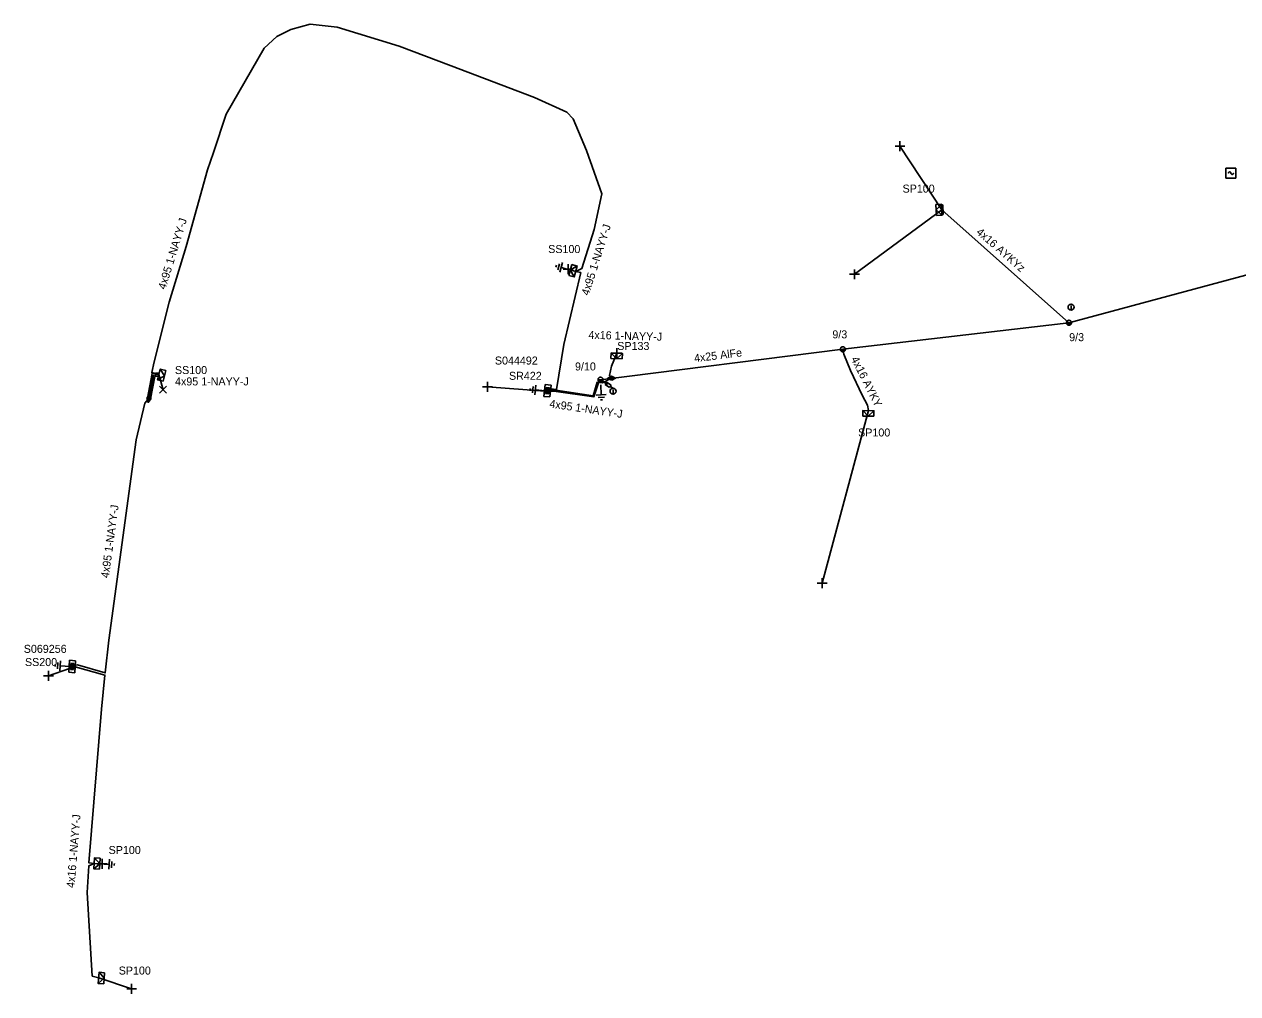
# Model space of a CAD drawing. Extents: x -717562 to -713845, y -1151196 to -1143903.
# Drawn here: x -717327.7 to -717176.1, y -1144131.3 to -1144010.2 of the extents above; entities that cross this region are included whole.
import ezdxf

# ---------------------------------------------------------------- set-up
doc = ezdxf.new("R2010")
doc.units = 0
for name, color, linetype in [('Vrstva 1', 7, 'Continuous'), ('Vrstva 10', 7, 'Continuous'), ('Vrstva 12', 7, 'Continuous'), ('Vrstva 13', 7, 'Continuous'), ('Vrstva 14', 7, 'Continuous'), ('Vrstva 15', 7, 'Continuous'), ('Vrstva 16', 7, 'Continuous'), ('Vrstva 19', 7, 'Continuous'), ('Vrstva 2', 7, 'Continuous'), ('Vrstva 20', 7, 'Continuous'), ('Vrstva 28', 7, 'Continuous'), ('Vrstva 29', 7, 'Continuous'), ('Vrstva 30', 7, 'Continuous'), ('Vrstva 31', 7, 'Continuous'), ('Vrstva 33', 7, 'Continuous'), ('Vrstva 34', 7, 'Continuous'), ('Vrstva 36', 7, 'Continuous'), ('Vrstva 4', 7, 'Continuous'), ('Vrstva 5', 7, 'Continuous'), ('Vrstva 52', 7, 'Continuous'), ('Vrstva 54', 7, 'Continuous'), ('Vrstva 55', 7, 'Continuous'), ('Vrstva 59', 7, 'Continuous'), ('Vrstva 6', 7, 'Continuous'), ('Vrstva 8', 7, 'Continuous'), ('Vrstva 9', 7, 'Continuous')]:
    doc.layers.add(name, color=color, linetype=linetype)

# ---------------------------------------------------------------- blocks, each defined once
blk = doc.blocks.new('NN440')
at = {"layer": 'Vrstva 2'}
for points in [[(0.63, 0), (0.63, 0.06), (0.62, 0.13), (0.6, 0.19), (0.58, 0.25), (0.55, 0.31), (0.51, 0.37), (0.47, 0.42), (0.42, 0.46), (0.37, 0.51), (0.32, 0.54), (0.26, 0.57), (0.2, 0.59), (0.13, 0.61), (0.07, 0.62), (0, 0.63), (-0.06, 0.62), (-0.13, 0.61), (-0.19, 0.59), (-0.26, 0.57), (-0.31, 0.54), (-0.37, 0.51), (-0.42, 0.46), (-0.47, 0.42), (-0.51, 0.37), (-0.54, 0.31), (-0.57, 0.25), (-0.6, 0.19), (-0.62, 0.13), (-0.63, 0.06), (-0.63, 0), (-0.63, -0.07), (-0.62, -0.14), (-0.6, -0.2), (-0.57, -0.26), (-0.54, -0.32), (-0.51, -0.37), (-0.47, -0.43), (-0.42, -0.47), (-0.37, -0.51), (-0.31, -0.55), (-0.26, -0.58), (-0.19, -0.6), (-0.13, -0.62), (-0.06, -0.63), (0, -0.63), (0.07, -0.63), (0.13, -0.62), (0.2, -0.6), (0.26, -0.58), (0.32, -0.55), (0.37, -0.51), (0.42, -0.47), (0.47, -0.43), (0.51, -0.37), (0.55, -0.32), (0.58, -0.26), (0.6, -0.2), (0.62, -0.14), (0.63, -0.07), (0.63, 0)], [(-0.63, 0), (0.63, 0)], [(-0.6, -0.18), (0.57, -0.18)], [(-0.51, -0.32), (0.5, -0.32)], [(-0.37, -0.47), (0.35, -0.47)]]:
    blk.add_lwpolyline(points, dxfattribs=at)
blk = doc.blocks.new('NN770')
at = {"layer": 'Vrstva 10'}
for p, q in [((0, 0.19), (0, 0.26)), ((0, -0.28), (0, 0.11))]:
    blk.add_line(p, q, dxfattribs=at)
blk.add_circle((0, -0.01), 0.375, dxfattribs=at)
blk = doc.blocks.new('NN870')
at = {"layer": 'Vrstva 4'}
for points in [[(0, -0.25), (0.5, 0), (0, 0.25), (-0.5, 0), (0, -0.25)], [(0.37, 0), (0, 0.19), (-0.36, 0), (0, -0.19), (0.37, 0)], [(0.24, 0), (0, 0.12), (-0.25, 0), (0, -0.12), (0.24, 0)], [(0.12, 0), (0, 0.06), (-0.13, 0), (0, -0.06), (0.12, 0)]]:
    blk.add_lwpolyline(points, dxfattribs=at)
blk = doc.blocks.new('NN800')
at = {"layer": 'Vrstva 1'}
for points in [[(-0.44, 0.44), (0.44, -0.44)], [(-0.44, -0.44), (0.44, 0.44)]]:
    blk.add_lwpolyline(points, dxfattribs=at)
blk = doc.blocks.new('NN820')
at = {"layer": 'Vrstva 13'}
for points in [[(0, 0), (0, -1.05)], [(-0.16, -0.81), (0.16, -0.81)], [(-0.16, -1.47), (-0.16, -0.81)], [(0.16, -1.47), (-0.16, -1.47)], [(0, -1.05), (-0.06, -0.93)], [(0, -1.05), (0.06, -0.93)], [(0, -1.47), (0, -1.87)], [(0.16, -0.81), (0.16, -1.47)]]:
    blk.add_lwpolyline(points, dxfattribs=at)
blk = doc.blocks.new('NN620')
at = {"layer": 'Vrstva 8'}
for points in [[(0.75, 0), (-0.75, 0)], [(-0.75, 0), (-0.75, -0.75)], [(0.75, -0.75), (0.75, 0)], [(-0.75, -0.75), (0.75, -0.75)], [(0.37, -0.18), (-0.38, -0.18)], [(-0.38, -0.18), (-0.38, -0.56)], [(-0.38, -0.56), (0.37, -0.56)], [(0.32, -0.23), (-0.33, -0.23)], [(-0.33, -0.23), (-0.33, -0.51)], [(-0.33, -0.51), (0.32, -0.51)], [(0.27, -0.27), (-0.28, -0.27)], [(-0.28, -0.27), (-0.28, -0.46)], [(-0.28, -0.46), (0.27, -0.46)], [(0.23, -0.32), (-0.23, -0.32)], [(-0.23, -0.32), (-0.23, -0.42)], [(-0.23, -0.42), (0.23, -0.42)], [(-0.19, -0.37), (0.19, -0.37)], [(0.23, -0.42), (0.23, -0.32)], [(0.27, -0.46), (0.27, -0.27)], [(0.32, -0.51), (0.32, -0.23)], [(0.37, -0.56), (0.37, -0.18)]]:
    blk.add_lwpolyline(points, dxfattribs=at)
blk = doc.blocks.new('NN630')
at = {"layer": 'Vrstva 9'}
for points in [[(0, -0.7), (-0.7, 0)], [(-0.7, -0.7), (-0.7, 0), (0.7, 0), (0.7, -0.7)], [(-0.7, -0.7), (0.7, -0.7)], [(0, -0.7), (0.7, 0)]]:
    blk.add_lwpolyline(points, dxfattribs=at)
blk = doc.blocks.new('NN810')
at = {"layer": 'Vrstva 14'}
for points in [[(0, -0.64), (0, -1.89)], [(0.63, -1.89), (-0.62, -1.89)], [(0.39, -2.2), (-0.4, -2.2)], [(0, -2.52), (-0.12, -2.52)], [(0.14, -2.52), (0, -2.52)]]:
    blk.add_lwpolyline(points, dxfattribs=at)
blk = doc.blocks.new('NN740')
at = {"layer": 'Vrstva 1'}
for points in [[(0.62, 0.62), (-0.63, 0.62)], [(-0.63, 0.62), (-0.63, -0.63)], [(0, 0), (0, 0.01), (0, 0.03), (-0.01, 0.05), (-0.01, 0.06), (-0.02, 0.08), (-0.03, 0.09), (-0.04, 0.1), (-0.05, 0.11), (-0.06, 0.12), (-0.08, 0.13), (-0.09, 0.14), (-0.11, 0.14), (-0.12, 0.15), (-0.14, 0.15), (-0.15, 0.15), (-0.17, 0.15), (-0.18, 0.15), (-0.2, 0.15), (-0.21, 0.14), (-0.23, 0.13), (-0.24, 0.12), (-0.26, 0.11), (-0.27, 0.1), (-0.28, 0.09), (-0.29, 0.08), (-0.29, 0.06), (-0.3, 0.05), (-0.3, 0.03), (-0.31, 0.02), (-0.31, 0), (-0.31, 0)], [(0.62, -0.63), (0.62, 0.62)], [(-0.63, -0.63), (0.62, -0.63)], [(0, 0), (0, -0.02), (0, -0.03), (0.01, -0.05), (0.01, -0.06), (0.02, -0.08), (0.03, -0.09), (0.04, -0.1), (0.05, -0.11), (0.06, -0.12), (0.07, -0.13), (0.09, -0.14), (0.1, -0.15), (0.12, -0.15), (0.13, -0.15), (0.15, -0.15), (0.16, -0.15), (0.18, -0.15), (0.19, -0.15), (0.21, -0.14), (0.22, -0.14), (0.24, -0.13), (0.25, -0.12), (0.26, -0.11), (0.27, -0.09), (0.28, -0.08), (0.29, -0.07), (0.29, -0.05), (0.3, -0.04), (0.3, -0.02), (0.3, -0.01), (0.3, -0.01)]]:
    blk.add_lwpolyline(points, dxfattribs=at)
blk = doc.blocks.new('NN515')
at = {"layer": 'Vrstva 2'}
for points in [[(-0.59, 0.18), (0.59, 0.18)], [(-0.59, 0.18), (-0.59, -0.18)], [(0.59, 0.18), (0.59, -0.18)]]:
    blk.add_lwpolyline(points, dxfattribs=at)

msp = doc.modelspace()

# ---------------------------------------------------------------- linework, layer by layer
at = {"layer": 'Vrstva 1'}
msp.add_lwpolyline([(-717255.69, -1144054.58), (-717225.41, -1144050.77), (-717197.16, -1144047.46), (-717165.94, -1144039.07)], dxfattribs=at)
at = {"layer": 'Vrstva 20'}
msp.add_lwpolyline([(-717312.32, -1144056.88), (-717311.71, -1144053.81), (-717310.89, -1144053.72), (-717310.85, -1144054.12), (-717311.37, -1144054.17), (-717311.92, -1144056.96)], close=True, dxfattribs=at)
at = {"layer": 'Vrstva 5'}
for points in [[(-717261.93, -1144055.73), (-717261.2, -1144055.78), (-717260.26, -1144050.17), (-717258.17, -1144041.19), (-717258.79, -1144041.05), (-717258.02, -1144040.7), (-717256.47, -1144035.82), (-717255.51, -1144031.34), (-717257.43, -1144025.93), (-717259.11, -1144022), (-717259.9, -1144021.13), (-717263.94, -1144019.33), (-717274.36, -1144015.37), (-717280.87, -1144012.92), (-717288.59, -1144010.55), (-717291.96, -1144010.17), (-717294.39, -1144010.81), (-717296.14, -1144011.71), (-717297.71, -1144013.16), (-717302.49, -1144021.38), (-717304.04, -1144026.17), (-717304.8, -1144028.37), (-717307.48, -1144037.93), (-717309.61, -1144044.87), (-717311.46, -1144052.35), (-717311.77, -1144053.69), (-717310.87, -1144053.92)], [(-717310.87, -1144053.92), (-717311.54, -1144053.99), (-717312.12, -1144056.92)], [(-717255.69, -1144054.58), (-717255.95, -1144054.97), (-717256.53, -1144056.72), (-717261.24, -1144056.04), (-717261.95, -1144055.99)], [(-717312.12, -1144056.92), (-717312.65, -1144057.49), (-717313.71, -1144062.1), (-717317.13, -1144087.11), (-717317.59, -1144091.2), (-717321.06, -1144090.21), (-717321.35, -1144090.24)], [(-717321.33, -1144090.43), (-717317.62, -1144091.48), (-717318.03, -1144095.75), (-717319.63, -1144114.95), (-717318.96, -1144115), (-717319.65, -1144115.31), (-717319.86, -1144118.63), (-717319.21, -1144129.08), (-717318.4, -1144129.31)]]:
    msp.add_lwpolyline(points, dxfattribs=at)
at = {"layer": 'Vrstva 52'}
for points in [[(-717261.94, -1144055.87), (-717261.27, -1144055.9), (-717256.61, -1144056.58), (-717256.1, -1144054.87), (-717255.46, -1144054.96), (-717254.3, -1144054.4), (-717254.55, -1144054.06), (-717254.3, -1144052.89), (-717253.66, -1144051.26)], [(-717225.41, -1144050.77), (-717225.29, -1144051.37), (-717224.47, -1144053.44), (-717223, -1144056.51), (-717222.33, -1144057.76), (-717222.22, -1144058.44)]]:
    msp.add_lwpolyline(points, dxfattribs=at)
at = {"layer": 'Vrstva 54'}
msp.add_lwpolyline([(-717197.16, -1144047.46), (-717213.06, -1144033.34)], dxfattribs=at)
at = {"layer": 'Vrstva 59'}
for points in [[(-717213.06, -1144033.34), (-717218.27, -1144025.41)], [(-717213.06, -1144033.34), (-717223.96, -1144041.41)], [(-717258.79, -1144041.05), (-717259.75, -1144040.78)], [(-717310.87, -1144053.92), (-717310.35, -1144055.83)], [(-717262.67, -1144056.02), (-717269.83, -1144055.47)], [(-717222.22, -1144058.44), (-717228, -1144080)], [(-717322.04, -1144090.67), (-717324.66, -1144091.56)], [(-717318.96, -1144115), (-717317.96, -1144115.06)], [(-717318.4, -1144129.31), (-717314.28, -1144130.66)]]:
    msp.add_lwpolyline(points, dxfattribs=at)

# ---------------------------------------------------------------- block references
at = {"layer": 'Vrstva 13', "rotation": -87.47005001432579}
msp.add_blockref('NN515', (-717213.06, -1144033.34), dxfattribs=at)
at = {"layer": 'Vrstva 13', "xscale": 0.5}
for p, yscale, rotation in [((-717197.16, -1144047.46), 0.5, 4.378188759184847), ((-717225.41, -1144050.77), 0.5000000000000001, 2.880561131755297), ((-717255.69, -1144054.58), 0.5, 2.678752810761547)]:
    msp.add_blockref('NN440', p, dxfattribs=dict(at, yscale=yscale, rotation=rotation))
at = {"layer": 'Vrstva 15'}
for p, rotation in [((-717258.79, -1144041.05), -105.45396948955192), ((-717261.95, -1144055.99), -94.02826392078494), ((-717255.69, -1144054.58), 2.6787528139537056), ((-717321.33, -1144090.43), -93.69529719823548), ((-717318.96, -1144115), 86.30470279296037)]:
    msp.add_blockref('NN810', p, dxfattribs=dict(at, rotation=rotation))
at = {"layer": 'Vrstva 16', "rotation": 56.214104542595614}
msp.add_blockref('NN820', (-717255.69, -1144054.58), dxfattribs=at)
at = {"layer": 'Vrstva 19'}
for p, rotation in [((-717254.3, -1144054.4), 1.4740722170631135), ((-717312.12, -1144056.92), 78.80292840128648)]:
    msp.add_blockref('NN870', p, dxfattribs=dict(at, rotation=rotation))
at = {"layer": 'Vrstva 28'}
for p, rotation in [((-717261.95, -1144055.99), -96.34395832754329), ((-717321.33, -1144090.43), -93.69529720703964)]:
    msp.add_blockref('NN620', p, dxfattribs=dict(at, rotation=rotation))
at = {"layer": 'Vrstva 31'}
for p, rotation in [((-717213.06, -1144033.34), -87.47005001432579), ((-717258.79, -1144041.05), -105.45396948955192), ((-717253.66, -1144051.26), -2.2433000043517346), ((-717310.87, -1144053.92), 76.31598021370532), ((-717222.22, -1144058.44), -0.5926834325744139), ((-717318.96, -1144115), 86.30470279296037), ((-717318.4, -1144129.31), 86.30470279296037)]:
    msp.add_blockref('NN630', p, dxfattribs=dict(at, rotation=rotation))
at = {"layer": 'Vrstva 34'}
for p, rotation in [((-717218.27, -1144025.41), 44.99999995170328), ((-717259.75, -1144040.78), 44.99999995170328), ((-717223.96, -1144041.41), 45), ((-717253.66, -1144051.26), 45), ((-717269.83, -1144055.47), 44.99999995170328), ((-717228, -1144080), 45), ((-717324.66, -1144091.56), 45), ((-717317.96, -1144115.06), 45), ((-717314.28, -1144130.66), 45)]:
    msp.add_blockref('NN800', p, dxfattribs=dict(at, rotation=rotation))
for name, p in [('NN740', (-717176.91, -1144028.77)), ('NN800', (-717310.35, -1144055.83))]:
    msp.add_blockref(name, p, dxfattribs=at)
at = {"layer": 'Vrstva 36'}
for p in [(-717196.9, -1144045.5), (-717254.13, -1144056)]:
    msp.add_blockref('NN770', p, dxfattribs=at)

# ---------------------------------------------------------------- texts
at = {"layer": 'Vrstva 12'}
for s, p in [('9/3', (-717226.72, -1144049.41)), ('9/3', (-717197.13, -1144049.76)), ('9/10', (-717258.88, -1144053.42))]:
    msp.add_text(s, height=1, dxfattribs=at).set_placement(p)
at = {"layer": 'Vrstva 2'}
msp.add_text('4x25 AlFe', height=1, rotation=7.172, dxfattribs=at).set_placement((-717243.94, -1144052.4))
at = {"layer": 'Vrstva 29'}
for s, p in [('S044492', (-717268.89, -1144052.68)), ('S069256', (-717327.76, -1144088.7))]:
    msp.add_text(s, height=1, dxfattribs=at).set_placement(p)
at = {"layer": 'Vrstva 30'}
for s, p in [('SR422', (-717267.13, -1144054.59)), ('SS200', (-717327.61, -1144090.35))]:
    msp.add_text(s, height=1, dxfattribs=at).set_placement(p)
at = {"layer": 'Vrstva 33'}
for s, p in [('SP100', (-717217.95, -1144031.2)), ('SS100', (-717262.23, -1144038.75)), ('SP133', (-717253.6, -1144050.86)), ('SS100', (-717308.87, -1144053.87)), ('SP100', (-717223.5, -1144061.67)), ('SP100', (-717317.16, -1144113.83)), ('SP100', (-717315.9, -1144128.89))]:
    msp.add_text(s, height=1, dxfattribs=at).set_placement(p)
at = {"layer": 'Vrstva 54'}
for s, rotation, p in [('4x16 1-NAYY-J', 358.457, (-717257.21, -1144049.46)), ('4x16 AYKY', 296.653, (-717224.42, -1144051.97))]:
    msp.add_text(s, height=1, rotation=rotation, dxfattribs=at).set_placement(p)
at = {"layer": 'Vrstva 55'}
msp.add_text('4x16 AYKYz', height=1, rotation=318.849, dxfattribs=at).set_placement((-717208.82, -1144036.26))
at = {"layer": 'Vrstva 6'}
for s, rotation, p in [('4x95 1-NAYY-J', 72.938, (-717310.06, -1144043.38)), ('4x95 1-NAYY-J', 72.432, (-717257.16, -1144044.13)), ('4x95 1-NAYY-J', 351.785, (-717262.13, -1144058.04)), ('4x95 1-NAYY-J', 82.213, (-717317.14, -1144079.4)), ('4x16 1-NAYY-J', 85.236, (-717321.43, -1144118.1))]:
    msp.add_text(s, height=1, rotation=rotation, dxfattribs=at).set_placement(p)
msp.add_text('4x95 1-NAYY-J', height=1, dxfattribs=at).set_placement((-717308.86, -1144055.29))

doc.saveas('drawing.dxf')
